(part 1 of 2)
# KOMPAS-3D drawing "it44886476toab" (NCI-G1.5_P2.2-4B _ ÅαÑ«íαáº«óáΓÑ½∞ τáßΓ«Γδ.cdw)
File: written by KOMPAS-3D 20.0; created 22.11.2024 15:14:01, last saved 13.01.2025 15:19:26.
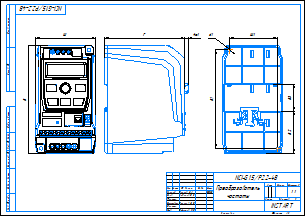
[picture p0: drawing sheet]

Sheet 1: A3, landscape

Document properties: Автор: admin; Полное имя файла: C:\Уралов Работа\Уралов (локальная)\ПЧ\! Китай 3Д-модель NCI\NCI 0.75-2.2 4B\NCI 0.75-2.2 4B.m3d

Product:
- Part/product: it44886476toab
    Масса: 2.32322
  - Body: Тело 17
      Масса: 0.0117014
  - Body: Тело 374
      Масса: 5.48304e-05
  - Body: Тело 265
      Масса: 1.32696e-05
  - Body: Тело 266
      Масса: 1.7366e-05
  - Body: Тело 267
      Масса: 1.7366e-05
  - Body: Тело 103
      Масса: 1.32696e-05
  - Body: Тело 573
      Масса: 4.06595e-05
  - Body: Тело 348
      Масса: 1.32696e-05
  - Body: Тело 270
      Масса: 1.7366e-05
  - Body: Тело 77
      Масса: 1.32696e-05
  - Body: Тело 244
      Масса: 1.65581e-05
  - Body: Тело 536
      Масса: 0.000158536
  - Body: Тело 377
      Масса: 1.65581e-05
  - Body: Тело 272
      Масса: 1.7366e-05
  - Body: Тело 273
      Масса: 5.48304e-05
  - Body: Тело 238
      Масса: 1.7366e-05
  - Body: Тело 274
      Масса: 1.7366e-05
  - Body: Тело 277
      Масса: 1.7366e-05
  - Body: Тело 530
      Масса: 5.61948e-05
  - Body: Тело 278
      Масса: 1.7366e-05
  - Body: Тело 282
      Масса: 1.7366e-05
  - Body: Тело 477
      Масса: 1.51773e-05
  - Body: Тело 526
      Масса: 5.61948e-05
  - Body: Тело 391
      Масса: 1.32696e-05
  - Body: Тело 285
      Масса: 5.48304e-05
  - Body: Тело 287
      Масса: 1.32696e-05
  - Body: Тело 290
      Масса: 0.000413213
  - Body: Тело 269
      Масса: 5.48304e-05
  - Body: Тело 292
      Масса: 1.7366e-05
  - Body: Тело 33
      Масса: 0.00516019
  - Body: Тело 252
      Масса: 5.48304e-05
  - Body: Тело 294
      Масса: 0.000413213
  - Body: Тело 297
      Масса: 3.64631e-05
  - Body: Тело 299
      Масса: 3.64028e-05
  - Body: Тело 283
      Масса: 1.7366e-05
  - Body: Тело 300
      Масса: 1.65581e-05
  - Body: Тело 303
      Масса: 1.65581e-05
  - Body: Тело 516
      Масса: 0.00507377
  - Body: Тело 384
      Масса: 5.48304e-05
  - Body: Тело 360
      Масса: 1.32696e-05
  - Body: Тело 347
      Масса: 1.32696e-05
  - Body: Тело 304
      Масса: 1.65581e-05
  - Body: Тело 307
      Масса: 0.000213463
  - Body: Тело 308
      Масса: 0.000413213
  - Body: Тело 180
      Масса: 1.32696e-05
  - Body: Тело 240
      Масса: 1.7366e-05
  - Body: Тело 309
      Масса: 1.32696e-05
  - Body: Тело 473
      Масса: 0.00425494
  - Body: Тело 311
      Масса: 5.48304e-05
  - Body: Тело 122
      Масса: 1.65581e-05
  - Body: Тело 560
      Масса: 1.65581e-05
  - Body: Тело 312
      Масса: 5.48304e-05
  - Body: Тело 317
      Масса: 1.32696e-05
  - Body: Тело 318
      Масса: 1.32696e-05
  - Body: Тело 321
      Масса: 1.32696e-05
  - Body: Тело 324
      Масса: 1.32696e-05
  - Body: Тело 480
      Масса: 1.51773e-05
  - Body: Тело 288
      Масса: 1.7366e-05
  - Body: Тело 293
      Масса: 5.48304e-05
  - Body: Тело 325
      Масса: 1.32696e-05
  - Body: Тело 99
      Масса: 1.65581e-05
  - Body: Тело 617
      Масса: 1.63919e-05
  - Body: Тело 327
      Масса: 1.32696e-05
  - Body: Тело 31
      Масса: 0.0078835
  - Body: Тело 100
      Масса: 1.65581e-05
  - Body: Тело 105
      Масса: 1.32696e-05
  - Body: Тело 328
      Масса: 1.7366e-05
  - Body: Тело 301
      Масса: 1.65581e-05
  - Body: Тело 331
      Масса: 1.7366e-05
  - Body: Тело 332
      Масса: 1.7366e-05
  - Body: Тело 446
      Масса: 0.000307437
  - Body: Тело 337
      Масса: 1.7366e-05
  - Body: Тело 338
      Масса: 1.7366e-05
  - Body: Тело 570
      Масса: 4.06595e-05
  - Body: Тело 340
      Масса: 1.32696e-05
  - Body: Тело 196
      Масса: 1.32696e-05
  - Body: Тело 357
      Масса: 1.65581e-05
  - Body: Тело 346
      Масса: 1.32696e-05
  - Body: Тело 335
      Масса: 1.32696e-05
  - Body: Тело 281
      Масса: 1.32696e-05
  - Body: Тело 362
      Масса: 1.32696e-05
  - Body: Тело 353
      Масса: 1.7366e-05
  - Body: Тело 355
      Масса: 5.48304e-05
  - Body: Тело 466
      Масса: 0.00829114
  - Body: Тело 358
      Масса: 5.48304e-05
  - Body: Тело 359
      Масса: 1.7366e-05
  - Body: Тело 286
      Масса: 1.7366e-05
  - Body: Тело 86
      Масса: 1.32696e-05
  - Body: Тело 310
      Масса: 1.7366e-05
  - Body: Тело 368
      Масса: 1.32696e-05
  - Body: Тело 370
      Масса: 1.32696e-05
  - Body: Тело 333
      Масса: 1.32696e-05
  - Body: Тело 628
      Масса: 1.51773e-05
  - Body: Тело 371
      Масса: 1.7366e-05
  - Body: Тело 75
      Масса: 1.32696e-05
  - Body: Тело 373
      Масса: 1.32696e-05
  - Body: Тело 375
      Масса: 1.32696e-05
  - Body: Тело 351
      Масса: 2.90876e-05
  - Body: Тело 76
      Масса: 1.65581e-05
  - Body: Тело 259
      Масса: 1.7366e-05
  - Body: Тело 378
      Масса: 0.000413213
  - Body: Тело 95
      Масса: 0.000935996
  - Body: Тело 372
      Масса: 1.7366e-05
  - Body: Тело 322
      Масса: 1.32696e-05
  - Body: Тело 380
      Масса: 1.32696e-05
  - Body: Тело 639
      Масса: 1.63919e-05
  - Body: Тело 385
      Масса: 1.32696e-05
  - Body: Тело 291
      Масса: 0.000213463
  - Body: Тело 386
      Масса: 1.32696e-05
  - Body: Тело 229
      Масса: 1.32696e-05
  - Body: Тело 388
      Масса: 1.32696e-05
  - Body: Тело 389
      Масса: 1.65581e-05
  - Body: Тело 93
      Масса: 3.83377e-05
  - Body: Тело 390
      Масса: 1.65581e-05
  - Body: Тело 143
      Масса: 1.32696e-05
  - Body: Тело 394
      Масса: 1.32696e-05
  - Body: Тело 395
      Масса: 1.32696e-05
  - Body: Тело 354
      Масса: 0.000213463
  - Body: Тело 396
      Масса: 1.7366e-05
  - Body: Тело 397
      Масса: 1.32696e-05
  - Body: Тело 398
      Масса: 1.65581e-05
  - Body: Тело 479
      Масса: 1.51773e-05
  - Body: Тело 402
      Масса: 1.7366e-05
  - Body: Тело 59
      Масса: 1.32696e-05
  - Body: Тело 339
      Масса: 1.32696e-05
  - Body: Тело 404
      Масса: 1.32696e-05
  - Body: Тело 89
      Масса: 0.00142218
  - Body: Тело 406
      Масса: 1.65581e-05
  - Body: Тело 393
      Масса: 1.32696e-05
  - Body: Тело 52
      Масса: 1.32696e-05
  - Body: Тело 407
      Масса: 5.48304e-05
  - Body: Тело 97
      Масса: 0.0015961
  - Body: Тело 410
      Масса: 5.48304e-05
  - Body: Тело 636
      Масса: 1.65581e-05
  - Body: Тело 412
      Масса: 1.7366e-05
  - Body: Тело 413
      Масса: 1.32696e-05
  - Body: Тело 414
      Масса: 1.32696e-05
  - Body: Тело 537
      Масса: 0.000158536
  - Body: Тело 415
      Масса: 1.7366e-05
  - Body: Тело 235
      Масса: 1.7366e-05
  - Body: Тело 419
      Масса: 1.32696e-05
  - Body: Тело 648
      Масса: 0.00426189
  - Body: Тело 420
      Масса: 1.7366e-05
  - Body: Тело 186
      Масса: 1.32696e-05
  - Body: Тело 422
      Масса: 5.48304e-05
  - Body: Тело 381
      Масса: 1.7366e-05
  - Body: Тело 423
      Масса: 1.32696e-05
  - Body: Тело 424
      Масса: 1.7366e-05
  - Body: Тело 98
      Масса: 1.65581e-05
  - Body: Тело 305
      Масса: 1.65581e-05
  - Body: Тело 425
      Масса: 1.32696e-05
  - Body: Тело 365
      Масса: 1.32696e-05
  - Body: Тело 271
      Масса: 1.32696e-05
  - Body: Тело 206
      Масса: 1.32696e-05
  - Body: Тело 429
      Масса: 0.146258
  - Body: Тело 334
      Масса: 1.7366e-05
  - Body: Тело 430
      Масса: 0.146258
  - Body: Тело 350
      Масса: 1.7366e-05
  - Body: Тело 345
      Масса: 1.32696e-05
  - Body: Тело 431
      Масса: 0.146258
  - Body: Тело 364
      Масса: 1.32696e-05
  - Body: Тело 329
      Масса: 1.32696e-05
  - Body: Тело 434
      Масса: 0.000355433
  - Body: Тело 5
      Масса: 0.000355433
  - Body: Тело 124
      Масса: 1.65581e-05
  - Body: Тело 344
      Масса: 1.32696e-05
  - Body: Тело 436
      Масса: 0.000355433
  - Body: Тело 439
      Масса: 0.00113358
  - Body: Тело 606
      Масса: 0.000137594
  - Body: Тело 323
      Масса: 1.32696e-05
  - Body: Тело 441
      Масса: 0.00113358
  - Body: Тело 442
      Масса: 0.000355433
  - Body: Тело 554
      Масса: 4.06595e-05
  - Body: Тело 444
      Масса: 0.000355433
  - Body: Тело 246
      Масса: 1.65581e-05
  - Body: Тело 445
      Масса: 0.00113358
  - Body: Тело 438
      Масса: 0.000355433
  - Body: Тело 106
      Масса: 1.32696e-05
  - Body: Тело 508
      Масса: 1.51773e-05
  - Body: Тело 577
      Масса: 1.7366e-05
  - Body: Тело 392
      Масса: 1.32696e-05
  - Body: Тело 193
      Масса: 1.32696e-05
  - Body: Тело 448
      Масса: 0.000307437
  - Body: Тело 481
      Масса: 1.51773e-05
  - Body: Тело 450
      Масса: 6.34685e-05
  - Body: Тело 222
      Масса: 1.32696e-05
  - Body: Тело 315
      Масса: 1.7366e-05
  - Body: Тело 452
      Масса: 1.63919e-05
  - Body: Тело 53
      Масса: 1.32696e-05
  - Body: Тело 401
      Масса: 1.32696e-05
  - Body: Тело 418
      Масса: 1.7366e-05
  - Body: Тело 517
      Масса: 0.00106884
  - Body: Тело 417
      Масса: 1.32696e-05
  - Body: Тело 453
      Масса: 1.63919e-05
  - Body: Тело 454
      Масса: 0.000382752
  - Body: Тело 428
      Масса: 0.146258
  - Body: Тело 455
      Масса: 1.51773e-05
  - Body: Тело 539
      Масса: 1.51773e-05
  - Body: Тело 457
      Масса: 1.51773e-05
  - Body: Тело 459
      Масса: 3.90329e-05
  - Body: Тело 557
      Масса: 0.00166679
  - Body: Тело 569
      Масса: 1.32696e-05
  - Body: Тело 578
      Масса: 1.32696e-05
  - Body: Тело 626
      Масса: 1.32696e-05
  - Body: Тело 134
      Масса: 1.32696e-05
  - Body: Тело 582
      Масса: 1.65581e-05
  - Body: Тело 203
      Масса: 1.32696e-05
  - Body: Тело 572
      Масса: 1.32696e-05
  - Body: Тело 567
      Масса: 1.32696e-05
  - Body: Тело 207
      Масса: 1.32696e-05
  - Body: Тело 645
      Масса: 1.32696e-05
  - Body: Тело 559
      Масса: 1.65581e-05
  - Body: Тело 152
      Масса: 1.32696e-05
  - Body: Тело 449
      Масса: 0.0658364
  - Body: Тело 316
      Масса: 1.32696e-05
  - Body: Тело 376
      Масса: 1.32696e-05
  - Body: Тело 575
      Масса: 1.32696e-05
  - Body: Тело 576
      Масса: 1.32696e-05
  - Body: Тело 85
      Масса: 1.32696e-05
  - Body: Тело 574
      Масса: 4.06595e-05
  - Body: Тело 399
      Масса: 1.32696e-05
  - Body: Тело 320
      Масса: 1.32696e-05
  - Body: Тело 275
      Масса: 1.7366e-05
  - Body: Тело 213
      Масса: 1.32696e-05
  - Body: Тело 625
      Масса: 1.32696e-05
  - Body: Тело 644
      Масса: 0.000158536
  - Body: Тело 584
      Масса: 4.06595e-05
  - Body: Тело 70
      Масса: 1.65581e-05
  - Body: Тело 588
      Масса: 1.32696e-05
  - Body: Тело 276
      Масса: 1.7366e-05
  - Body: Тело 363
      Масса: 1.32696e-05
  - Body: Тело 474
      Масса: 1.51773e-05
  - Body: Тело 548
      Масса: 2.98222e-05
  - Body: Тело 409
      Масса: 5.48304e-05
  - Body: Тело 472
      Масса: 0.00329327
  - Body: Тело 533
      Масса: 5.61948e-05
  - Body: Тело 647
      Масса: 0.00426189
  - Body: Тело 586
      Масса: 1.32696e-05
  - Body: Тело 262
      Масса: 1.7366e-05
  - Body: Тело 562
      Масса: 0.000382752
  - Body: Тело 379
      Масса: 1.32696e-05
  - Body: Тело 632
      Масса: 1.51773e-05
  - Body: Тело 565
      Масса: 4.06595e-05
  - Body: Тело 118
      Масса: 0.000413213
  - Body: Тело 597
      Масса: 7.12116e-06
  - Body: Тело 613
      Масса: 1.63919e-05
  - Body: Тело 387
      Масса: 1.32696e-05
  - Body: Тело 593
      Масса: 1.32696e-05
  - Body: Тело 408
      Масса: 5.48304e-05
  - Body: Тело 109
      Масса: 1.32696e-05
  - Body: Тело 163
      Масса: 1.32696e-05
  - Body: Тело 488
      Масса: 1.51773e-05
  - Body: Тело 367
      Масса: 1.32696e-05
  - Body: Тело 411
      Масса: 5.48304e-05
  - Body: Тело 583
      Масса: 4.06595e-05
  - Body: Тело 598
      Масса: 7.12116e-06
  - Body: Тело 551
      Масса: 0.000255388
  - Body: Тело 405
      Масса: 1.32696e-05
  - Body: Тело 619
      Масса: 1.32696e-05
  - Body: Тело 361
      Масса: 1.32696e-05
  - Body: Тело 589
      Масса: 1.32696e-05
  - Body: Тело 499
      Масса: 1.51773e-05
  - Body: Тело 440
      Масса: 0.000355433
  - Body: Тело 640
      Масса: 1.63919e-05
  - Body: Тело 150
      Масса: 1.32696e-05
  - Body: Тело 568
      Масса: 1.32696e-05
  - Body: Тело 194
      Масса: 1.32696e-05
  - Body: Тело 251
      Масса: 1.7366e-05
  - Body: Тело 342
      Масса: 0.00166679
  - Body: Тело 604
      Масса: 5.61948e-05
  - Body: Тело 650
      Масса: 0.00426189
  - Body: Тело 161
      Масса: 1.32696e-05
  - Body: Тело 611
      Масса: 0.000158536
  - Body: Тело 210
      Масса: 1.32696e-05
  - Body: Тело 540
      Масса: 1.51773e-05
  - Body: Тело 296
      Масса: 3.6965e-05
  - Body: Тело 601
      Масса: 5.61948e-05
  - Body: Тело 484
      Масса: 0.000158536
  - Body: Тело 622
      Масса: 1.32696e-05
  - Body: Тело 527
      Масса: 0.000141095
  - Body: Тело 624
      Масса: 1.32696e-05
  - Body: Тело 121
      Масса: 0.000413213
  - Body: Тело 600
      Масса: 5.61948e-05
  - Body: Тело 603
      Масса: 5.61948e-05
  - Body: Тело 607
      Масса: 1.32696e-05
  - Body: Тело 289
      Масса: 1.7366e-05
  - Body: Тело 471
      Масса: 0.00329327
  - Body: Тело 313
      Масса: 1.7366e-05
  - Body: Тело 591
      Масса: 7.12116e-06
  - Body: Тело 356
      Масса: 1.65581e-05
  - Body: Тело 306
      Масса: 1.65581e-05
  - Body: Тело 541
      Масса: 0.000158536
  - Body: Тело 511
      Масса: 1.51773e-05
  - Body: Тело 160
      Масса: 1.32696e-05
  - Body: Тело 566
      Масса: 1.32696e-05
  - Body: Тело 563
      Масса: 4.06595e-05
  - Body: Тело 638
      Масса: 1.7366e-05
  - Body: Тело 489
      Масса: 1.51773e-05
  - Body: Тело 456
      Масса: 1.51773e-05
  - Body: Тело 485
      Масса: 0.000158536
  - Body: Тело 284
      Масса: 1.7366e-05
  - Body: Тело 138
      Масса: 2.23009e-05
  - Body: Тело 225
      Масса: 1.32696e-05
  - Body: Тело 546
      Масса: 0.000255388
  - Body: Тело 113
      Масса: 0.000413213
  - Body: Тело 642
      Масса: 3.90329e-05
  - Body: Тело 618
      Масса: 1.63919e-05
  - Body: Тело 525
      Масса: 0.000213463
  - Body: Тело 164
      Масса: 1.32696e-05
  - Body: Тело 253
      Масса: 1.7366e-05
  - Body: Тело 561
      Масса: 1.65581e-05
  - Body: Тело 594
      Масса: 1.32696e-05
  - Body: Тело 482
      Масса: 1.51773e-05
  - Body: Тело 81
      Масса: 1.32696e-05
  - Body: Тело 280
      Масса: 1.32696e-05
  - Body: Тело 494
      Масса: 1.51773e-05
  - Body: Тело 641
      Масса: 3.90329e-05
  - Body: Тело 564
      Масса: 4.06595e-05
  - Body: Тело 633
      Масса: 1.51773e-05
  - Body: Тело 518
      Масса: 0.00166679
  - Body: Тело 620
      Масса: 1.7366e-05
  - Body: Тело 497
      Масса: 1.51773e-05
  - Body: Тело 151
      Масса: 1.65581e-05
  - Body: Тело 302
      Масса: 1.65581e-05
  - Body: Тело 110
      Масса: 1.32696e-05
  - Body: Тело 646
      Масса: 0.000137594
  - Body: Тело 264
      Масса: 1.7366e-05
  - Body: Тело 635
      Масса: 1.65581e-05
  - Body: Тело 608
      Масса: 0.00166679
  - Body: Тело 460
      Масса: 3.90329e-05
  - Body: Тело 403
      Масса: 1.7366e-05
  - Body: Тело 612
      Масса: 0.000158536
  - Body: Тело 492
      Масса: 1.51773e-05
  - Body: Тело 139
      Масса: 0.000194606
  - Body: Тело 400
      Масса: 1.7366e-05
  - Body: Тело 605
      Масса: 5.61948e-05
  - Body: Тело 623
      Масса: 1.32696e-05
  - Body: Тело 117
      Масса: 0.000413213
  - Body: Тело 185
      Масса: 1.32696e-05
  - Body: Тело 631
      Масса: 1.51773e-05
  - Body: Тело 580
      Масса: 1.32696e-05
  - Body: Тело 349
      Масса: 1.7366e-05
  - Body: Тело 621
      Масса: 1.32696e-05
  - Body: Тело 627
      Масса: 0.000255388
  - Body: Тело 531
      Масса: 5.61948e-05
  - Body: Тело 649
      Масса: 0.00426189
  - Body: Тело 585
      Масса: 4.06595e-05
  - Body: Тело 236
      Масса: 1.7366e-05
  - Body: Тело 513
      Масса: 1.51773e-05
  - Body: Тело 426
      Масса: 1.32696e-05
  - Body: Тело 341
      Масса: 0.00166679
  - Body: Тело 470
      Масса: 0.00329329
  - Body: Тело 382
      Масса: 5.48304e-05
  - Body: Тело 227
      Масса: 1.32696e-05
  - Body: Тело 476
      Масса: 1.51773e-05
  - Body: Тело 538
      Масса: 1.51773e-05
  - Body: Тело 596
      Масса: 1.32696e-05
  - Body: Тело 609
      Масса: 1.7366e-05
  - Body: Тело 610
      Масса: 0.00166679
  - Body: Тело 263
      Масса: 1.7366e-05
  - Body: Тело 629
      Масса: 1.51773e-05
  - Body: Тело 336
      Масса: 3.64028e-05
  - Body: Тело 495
      Масса: 1.51773e-05
  - Body: Тело 168
      Масса: 1.32696e-05
  - Body: Тело 298
      Масса: 3.64495e-05
  - Body: Тело 279
      Масса: 1.32696e-05
  - Body: Тело 72
      Масса: 1.65581e-05
  - Body: Тело 500
      Масса: 1.51773e-05
  - Body: Тело 505
      Масса: 1.51773e-05
  - Body: Тело 558
      Масса: 0.00726683
  - Body: Тело 630
      Масса: 1.51773e-05
  - Body: Тело 602
      Масса: 5.61948e-05
  - Body: Тело 556
      Масса: 0.00166679
  - Body: Тело 555
      Масса: 0.00166679
  - Body: Тело 634
      Масса: 1.51773e-05
  - Body: Тело 435
      Масса: 0.00113358
  - Body: Тело 416
      Масса: 1.7366e-05
  - Body: Тело 190
      Масса: 1.32696e-05
  - Body: Тело 330
      Масса: 1.7366e-05
  - Body: Тело 28
      Масса: 0.00135688
  - Body: Тело 553
      Масса: 4.06595e-05
  - Body: Тело 176
      Масса: 1.32696e-05
  - Body: Тело 552
      Масса: 4.06595e-05
  - Body: Тело 534
      Масса: 1.32696e-05
  - Body: Тело 595
      Масса: 1.32696e-05
  - Body: Тело 23
      Масса: 0.0243258
  - Body: Тело 247
      Масса: 1.7366e-05
  - Body: Тело 314
      Масса: 1.7366e-05
  - Body: Тело 126
      Масса: 0.000512664
  - Body: Тело 157
      Масса: 1.32696e-05
  - Body: Тело 550
      Масса: 0.000255388
  - Body: Тело 32
      Масса: 0.0135217
  - Body: Тело 592
      Масса: 7.12116e-06
  - Body: Тело 366
      Масса: 1.7366e-05
  - Body: Тело 504
      Масса: 1.51773e-05
  - Body: Тело 258
      Масса: 1.7366e-05
  - Body: Тело 421
      Масса: 1.7366e-05
  - Body: Тело 35
      Масса: 0.262997
  - Body: Тело 204
      Масса: 1.32696e-05
  - Body: Тело 549
      Масса: 0.000255388
  - Body: Тело 257
      Масса: 1.7366e-05
  - Body: Тело 614
      Масса: 1.63919e-05
  - Body: Тело 547
      Масса: 0.000255388
  - Body: Тело 41
      Масса: 0.0119524
  - Body: Тело 71
      Масса: 1.65581e-05
  - Body: Тело 506
      Масса: 1.51773e-05
  - Body: Тело 545
      Масса: 1.51773e-05
  - Body: Тело 145
      Масса: 1.32696e-05
  - Body: Тело 461
      Масса: 0.000404362
  - Body: Тело 502
      Масса: 1.51773e-05
  - Body: Тело 352
      Масса: 2.90876e-05
  - Body: Тело 120
      Масса: 0.000413213
  - Body: Тело 295
      Масса: 1.65581e-05
  - Body: Тело 544
      Масса: 0.000158536
  - Body: Тело 469
      Масса: 0.0113891
  - Body: Тело 146
      Масса: 1.32696e-05
  - Body: Тело 149
      Масса: 1.32696e-05
  - Body: Тело 615
      Масса: 1.63919e-05
  - Body: Тело 543
      Масса: 0.000158536
  - Body: Тело 542
      Масса: 0.000158536
  - Body: Тело 462
      Масса: 0.000404362
  - Body: Тело 616
      Масса: 1.63919e-05
  - Body: Тело 343
      Масса: 0.00166679
  - Body: Тело 532
      Масса: 5.61948e-05
  - Body: Тело 493
      Масса: 1.51773e-05
  - Body: Тело 529
      Масса: 5.61948e-05
  - Body: Тело 579
      Масса: 0.00017125
  - Body: Тело 200
      Масса: 1.32696e-05
  - Body: Тело 239
      Масса: 5.48304e-05
  - Body: Тело 443
      Масса: 0.00113358
  - Body: Тело 216
      Масса: 0.000280294
  - Body: Тело 468
      Масса: 0.0253857
  - Body: Тело 64
      Масса: 1.65581e-05
  - Body: Тело 528
      Масса: 0.000141095
  - Body: Тело 599
      Масса: 7.12116e-06
  - Body: Тело 590
      Масса: 1.32696e-05
  - Body: Тело 191
      Масса: 1.32696e-05
  - Body: Тело 523
      Масса: 0.000255388
  - Body: Тело 458
      Масса: 1.51773e-05
  - Body: Тело 319
      Масса: 1.32696e-05
  - Body: Тело 49
      Масса: 0.00944
  - Body: Тело 522
      Масса: 1.65581e-05
  - Body: Тело 521
      Масса: 1.32696e-05
  - Body: Тело 571
      Масса: 0.00166679
  - Body: Тело 509
      Масса: 1.51773e-05
  - Body: Тело 326
      Масса: 1.32696e-05
  - Body: Тело 520
      Масса: 5.48304e-05
  - Body: Тело 427
      Масса: 1.32696e-05
  - Body: Тело 519
      Масса: 1.7366e-05
  - Body: Тело 637
      Масса: 1.51773e-05
  - Body: Тело 524
      Масса: 1.65581e-05
  - Body: Тело 432
      Масса: 0.000118347
  - Body: Тело 487
      Масса: 1.65581e-05
  - Body: Тело 510
      Масса: 1.51773e-05
  - Body: Тело 515
      Масса: 0.00507372
  - Body: Тело 512
      Масса: 1.51773e-05
  - Body: Тело 155
      Масса: 1.32696e-05
  - Body: Тело 587
      Масса: 1.32696e-05
  - Body: Тело 174
      Масса: 1.65581e-05
  - Body: Тело 507
      Масса: 1.51773e-05
  - Body: Тело 12
      Масса: 0.000703761
  - Body: Тело 187
      Масса: 1.32696e-05
  - Body: Тело 447
      Масса: 0.000307437
  - Body: Тело 503
      Масса: 1.51773e-05
  - Body: Тело 501
      Масса: 1.51773e-05
  - Body: Тело 369
      Масса: 1.32696e-05
  - Body: Тело 60
      Масса: 1.32696e-05
  - Body: Тело 498
      Масса: 1.51773e-05
  - Body: Тело 535
      Масса: 1.52051e-05
  - Body: Тело 437
      Масса: 0.00113358
  - Body: Тело 496
      Масса: 1.51773e-05
  - Body: Тело 433
      Масса: 0.000118347
  - Body: Тело 491
      Масса: 1.65581e-05
  - Body: Тело 490
      Масса: 1.51773e-05
  - Body: Тело 581
      Масса: 1.65581e-05
  - Body: Тело 486
      Масса: 0.000158536
  - Body: Тело 483
      Масса: 1.51773e-05
  - Body: Тело 514
      Масса: 1.51773e-05
  - Body: Тело 643
      Масса: 0.000158536
  - Body: Тело 125
      Масса: 1.65581e-05
  - Body: Тело 383
      Масса: 0.000340816
  - Body: Тело 465
      Масса: 0.00829114
  - Body: Тело 478
      Масса: 1.51773e-05
  - Body: Тело 451
      Масса: 6.34685e-05
  - Body: Тело 475
      Масса: 1.51773e-05
  - Body: Тело 467
      Масса: 0.00436982
  - Body: Тело 268
      Масса: 5.48304e-05
  - Body: Тело 464
      Масса: 0.00829425
  - Body: Тело 226
      Масса: 0.000413213
  - Body: Тело 463
      Масса: 0.000404362
  - Body: Тело 170
      Масса: 1.32696e-05
  - Body: Тело 261
      Масса: 3.83377e-05
  - Body: Тело 260
      Масса: 1.7366e-05
  - Body: Тело 167
      Масса: 1.32696e-05
  - Body: Тело 256
      Масса: 1.7366e-05
  - Body: Тело 119
      Масса: 0.000413213
  - Body: Тело 255
      Масса: 1.7366e-05
  - Body: Тело 254
      Масса: 1.32696e-05
  - Body: Тело 250
      Масса: 1.7366e-05
  - Body: Тело 249
      Масса: 1.7366e-05
  - Body: Тело 248
      Масса: 1.7366e-05
  - Body: Тело 19
      Масса: 0.0117014
  - Body: Тело 114
      Масса: 0.000413213
  - Body: Тело 234
      Масса: 1.7366e-05
  - Body: Тело 245
      Масса: 1.65581e-05
  - Body: Тело 243
      Масса: 1.65581e-05
  - Body: Тело 242
      Масса: 1.65581e-05
  - Body: Тело 65
      Масса: 1.65581e-05
  - Body: Тело 241
      Масса: 0.000424983
  - Body: Тело 141
      Масса: 0.000213463
  - Body: Тело 237
      Масса: 1.7366e-05
  - Body: Тело 1
      Масса: 0.00113358
  - Body: Тело 233
      Масса: 1.7366e-05
  - Body: Тело 232
      Масса: 5.48304e-05
  - Body: Тело 231
      Масса: 0.00398049
  - Body: Тело 230
      Масса: 1.32696e-05
  - Body: Тело 184
      Масса: 1.32696e-05
  - Body: Тело 228
      Масса: 1.32696e-05
  - Body: Тело 224
      Масса: 1.32696e-05
  - Body: Тело 162
      Масса: 1.65581e-05
  - Body: Тело 223
      Масса: 1.32696e-05
  - Body: Тело 221
      Масса: 1.65581e-05
  - Body: Тело 220
      Масса: 1.32696e-05
  - Body: Тело 219
      Масса: 1.32696e-05
  - Body: Тело 218
      Масса: 1.32696e-05
  - Body: Тело 217
      Масса: 1.32696e-05
  - Body: Тело 215
      Масса: 1.65581e-05
  - Body: Тело 9
      Масса: 0.000703761
  - Body: Тело 214
      Масса: 1.32696e-05
  - Body: Тело 212
      Масса: 1.32696e-05
  - Body: Тело 211
      Масса: 1.32696e-05
  - Body: Тело 209
      Масса: 1.32696e-05
  - Body: Тело 208
      Масса: 1.7366e-05
  - Body: Тело 205
      Масса: 1.32696e-05
  - Body: Тело 202
      Масса: 1.32696e-05
  - Body: Тело 201
      Масса: 1.32696e-05
  - Body: Тело 29
      Масса: 0.00135688
  - Body: Тело 199
      Масса: 1.32696e-05
  - Body: Тело 198
      Масса: 1.32696e-05
  - Body: Тело 197
      Масса: 1.32696e-05
  - Body: Тело 195
      Масса: 1.32696e-05
  - Body: Тело 192
      Масса: 1.32696e-05
  - Body: Тело 189
      Масса: 1.32696e-05
  - Body: Тело 188
      Масса: 1.32696e-05
  - Body: Тело 183
      Масса: 1.32696e-05
  - Body: Тело 182
      Масса: 1.32696e-05
  - Body: Тело 181
      Масса: 1.32696e-05
  - Body: Тело 179
      Масса: 1.32696e-05
  - Body: Тело 178
      Масса: 1.32696e-05
  - Body: Тело 44
      Масса: 0.0119524
  - Body: Тело 50
      Масса: 0.00101975
  - Body: Тело 177
      Масса: 1.32696e-05
  - Body: Тело 175
      Масса: 1.32696e-05
  - Body: Тело 45
      Масса: 0.0267013
  - Body: Тело 137
      Масса: 1.32696e-05
  - Body: Тело 173
      Масса: 1.32696e-05
  - Body: Тело 172
      Масса: 1.65581e-05
  - Body: Тело 153
      Масса: 1.32696e-05
  - Body: Тело 171
      Масса: 1.32696e-05
  - Body: Тело 169
      Масса: 1.32696e-05
  - Body: Тело 140
      Масса: 0.000213463
  - Body: Тело 166
      Масса: 1.32696e-05
  - Body: Тело 165
      Масса: 1.65581e-05
  - Body: Тело 159
      Масса: 1.32696e-05
  - Body: Тело 116
      Масса: 0.000413213
  - Body: Тело 158
      Масса: 1.32696e-05
  - Body: Тело 156
      Масса: 1.32696e-05
  - Body: Тело 154
      Масса: 1.32696e-05
  - Body: Тело 148
      Масса: 1.32696e-05
  - Body: Тело 147
      Масса: 1.32696e-05
  - Body: Тело 24
      Масса: 0.0110484
  - Body: Тело 62
      Масса: 1.32696e-05
  - Body: Тело 144
      Масса: 1.32696e-05
  - Body: Тело 142
      Масса: 0.000213463
  - Body: Тело 136
      Масса: 1.32696e-05
  - Body: Тело 135
      Масса: 1.32696e-05
  - Body: Тело 38
      Масса: 0.00631989
  - Body: Тело 133
      Масса: 1.32696e-05
  - Body: Тело 132
      Масса: 1.32696e-05
  - Body: Тело 131
      Масса: 1.32696e-05
  - Body: Тело 16
      Масса: 0.000703761
  - Body: Тело 130
      Масса: 1.32696e-05
  - Body: Тело 112
      Масса: 0.000413213
  - Body: Тело 129
      Масса: 1.32696e-05
  - Body: Тело 128
      Масса: 1.32696e-05
  - Body: Тело 127
      Масса: 1.32696e-05
  - Body: Тело 123
      Масса: 1.65581e-05
  - Body: Тело 115
      Масса: 0.000413213
  - Body: Тело 111
      Масса: 0.000194606
  - Body: Тело 108
      Масса: 1.32696e-05
  - Body: Тело 107
      Масса: 1.32696e-05
  - Body: Тело 104
      Масса: 1.32696e-05
  - Body: Тело 102
      Масса: 1.32696e-05
  - Body: Тело 90
      Масса: 0.000966482
  - Body: Тело 101
      Масса: 1.32696e-05
  - Body: Тело 96
      Масса: 0.00181049
  - Body: Тело 94
      Масса: 0.00554276
  - Body: Тело 92
      Масса: 3.83377e-05
  - Body: Тело 91
      Масса: 0.0246688
  - Body: Тело 15
      Масса: 0.000703761
  - Body: Тело 88
      Масса: 0.000873873
  - Body: Тело 87
      Масса: 0.000966482
  - Body: Тело 84
      Масса: 1.32696e-05
  - Body: Тело 83
      Масса: 1.32696e-05
  - Body: Тело 82
      Масса: 1.32696e-05
  - Body: Тело 80
      Масса: 1.32696e-05
  - Body: Тело 79
      Масса: 1.32696e-05
  - Body: Тело 78
      Масса: 1.65581e-05
  - Body: Тело 74
      Масса: 1.65581e-05
  - Body: Тело 48
      Масса: 0.00853877
  - Body: Тело 73
      Масса: 1.65581e-05
  - Body: Тело 69
      Масса: 1.65581e-05
  - Body: Тело 68
      Масса: 1.65581e-05
  - Body: Тело 67
      Масса: 1.65581e-05
  - Body: Тело 66
      Масса: 1.65581e-05
  - Body: Тело 63
      Масса: 1.65581e-05
  - Body: Тело 57
      Масса: 1.32696e-05
  - Body: Тело 61
      Масса: 1.32696e-05
  - Body: Тело 58
      Масса: 1.32696e-05
  - Body: Тело 56
      Масса: 1.32696e-05
  - Body: Тело 55
      Масса: 1.32696e-05
  - Body: Тело 54
      Масса: 1.32696e-05
  - Body: Тело 51
      Масса: 1.32696e-05
  - Body: Тело 47
      Масса: 0.551587
  - Body: Тело 46
      Масса: 0.0119034
  - Body: Тело 43
      Масса: 0.0119524
  - Body: Тело 42
      Масса: 0.0119524
  - Body: Тело 40
      Масса: 0.0119524
  - Body: Тело 39
      Масса: 0.0119524
  - Body: Тело 37
      Масса: 0.0343584
  - Body: Тело 36
      Масса: 0.0668131
  - Body: Тело 34
      Масса: 0.00831628
  - Body: Тело 30
      Масса: 0.000935996
  - Body: Тело 27
      Масса: 0.00135688
  - Body: Тело 26
      Масса: 0.00135688
  - Body: Тело 25
      Масса: 0.00135688
  - Body: Тело 22
      Масса: 0.0636504
  - Body: Тело 21
      Масса: 0.0864411
  - Body: Тело 20
      Масса: 0.120334
  - Body: Тело 18
      Масса: 0.0117014
  - Body: Тело 14
      Масса: 0.000703761
  - Body: Тело 13
      Масса: 0.000703761
  - Body: Тело 11
      Масса: 0.000703761
  - Body: Тело 10
      Масса: 0.0160396
  - Body: Тело 8
      Масса: 0.000703761
  - Body: Тело 7
      Масса: 0.000703761
  - Body: Тело 6
      Масса: 0.000355433
  - Body: Тело 4
      Масса: 0.000355433
  - Body: Тело 3
      Масса: 0.00113358
  - Body: Тело 2
      Масса: 0.00113358

Title block, sheet 1: Наименование: Преобразователь / частоты; designation: NCI-G1.5/P2.2-4B; Количество листов документа: 1; organisation: INSTART; cell 10: Согласовано; Форматы листов документа: A3; stored path: P:\INSTART\Технический отдел\ОР\Прочие задачи\КД на номенклатурный ряд\КД на типоразмеры ПЧ\NCI\NCI-G0.75_P1.5-4B\NCI-G0.75_P1.5-4B _ Преобразователь частоты.cdw; Разработал: Уралов Д.А.; Проверил: Андреев Н.В.; Подписал: Смелков Ж.Е.; Утвердил: Ефремов И.Н.; Разработал, date: 13.01.25

Views: Вид 1
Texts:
  Кривая без истории:10000
  Кривая без истории:10001
  Кривая без истории:10002
  Кривая без истории:10003
  Кривая без истории:10004
  Кривая без истории:10005
  Кривая без истории:10006
  Кривая без истории:10007
  Кривая без истории:10008
  Кривая без истории:10009
  Кривая без истории:10010
  Кривая без истории:10011
  Кривая без истории:10012
  Кривая без истории:10013
  Кривая без истории:10014
  Кривая без истории:10015
  Кривая без истории:10016
  Кривая без истории:10017
  Кривая без истории:10018
  Кривая без истории:10019
  Кривая без истории:10020
  Кривая без истории:10021
  Кривая без истории:10022
  Кривая без истории:10023
  Кривая без истории:10024
  Кривая без истории:10025
  Кривая без истории:10026
  Кривая без истории:10027
  Кривая без истории:10028
  Кривая без истории:10029
  Кривая без истории:10030
  Кривая без истории:10031
  Кривая без истории:10032
  Кривая без истории:10033
  Кривая без истории:10034
  Кривая без истории:10035
  Кривая без истории:10036
  Кривая без истории:10037
  Кривая без истории:10038
  Кривая без истории:10039
  Кривая без истории:10040
  Кривая без истории:10041
  Кривая без истории:10042
  Кривая без истории:10043
  Кривая без истории:10044
  Кривая без истории:10045
  Кривая без истории:10046
  Кривая без истории:10047
  Кривая без истории:10048
  Кривая без истории:10049
  Кривая без истории:10050
  Кривая без истории:10051
  Кривая без истории:10052
  Кривая без истории:10053
  Кривая без истории:10054
  Кривая без истории:10055
  Кривая без истории:10056
  Кривая без истории:10057
  Кривая без истории:10058
  Кривая без истории:10059
  Кривая без истории:10060
  Кривая без истории:10061
  Кривая без истории:10062
  Кривая без истории:10063
  Кривая без истории:10064
  Кривая без истории:10065
  Кривая без истории:10066
  Кривая без истории:10067
  Кривая без истории:10068
  Кривая без истории:10069
  Кривая без истории:10070
  Кривая без истории:10071
  Кривая без истории:10072
  Кривая без истории:10073
  Кривая без истории:10074
  Кривая без истории:10075
  Кривая без истории:10076
  Кривая без истории:10077
  Кривая без истории:10078
  Кривая без истории:10079
  Кривая без истории:10080
  Кривая без истории:10081
  Кривая без истории:10082
  Кривая без истории:10083
  Кривая без истории:10084
  Кривая без истории:10085
  Кривая без истории:10086
  Кривая без истории:10087
  Кривая без истории:10088
  Кривая без истории:10089
  Кривая без истории:10090
  Кривая без истории:10091
  Кривая без истории:10092
  Кривая без истории:10093
  Кривая без истории:10094
  Кривая без истории:10095
  Кривая без истории:10096
  Кривая без истории:10097
  Кривая без истории:10098
  Кривая без истории:10099
  Кривая без истории:10100
  Кривая без истории:10101
  Кривая без истории:10102
  Кривая без истории:10103
  Кривая без истории:10104
  Кривая без истории:10105
  Кривая без истории:10106
  Кривая без истории:10107
  Кривая без истории:10108
  Кривая без истории:10109
  Кривая без истории:10110
  Кривая без истории:10111
  Кривая без истории:10112
  Кривая без истории:10113
  Кривая без истории:10114
  Кривая без истории:10115
  Кривая без истории:10116
  Кривая без истории:10117
  Кривая без истории:10118
  Кривая без истории:10119
  Кривая без истории:10120
  Кривая без истории:10121
  Кривая без истории:10122
  Кривая без истории:10123
  Кривая без истории:10124
  Кривая без истории:10125
  Кривая без истории:10126
  Кривая без истории:10127
  Кривая без истории:10128
  Кривая без истории:10129
  Кривая без истории:10130
  Кривая без истории:10131
  Кривая без истории:10132
  Кривая без истории:10133
  Кривая без истории:10134
  Кривая без истории:10135
  Кривая без истории:10136
  Кривая без истории:10137
  Кривая без истории:10138
  Кривая без истории:10139
  Кривая без истории:10140
  Кривая без истории:10141
  Кривая без истории:10142
  Кривая без истории:10143
  Кривая без истории:10144
  Кривая без истории:10145
  Кривая без истории:10146
  Кривая без истории:10147
  Кривая без истории:10148
  Кривая без истории:10149
  Кривая без истории:10150
  Кривая без истории:10151
  Кривая без истории:10152
  Кривая без истории:10153
  Кривая без истории:10154
  Кривая без истории:10155
  Кривая без истории:10156
  Кривая без истории:10157
  Кривая без истории:10158
  Кривая без истории:10159
  Кривая без истории:10160
  Кривая без истории:10161
  Кривая без истории:10162
  Кривая без истории:10163
  Кривая без истории:10164
  Кривая без истории:10165
  Кривая без истории:10166
  Кривая без истории:10167
  Кривая без истории:10168
  Кривая без истории:10169
  Кривая без истории:10170
  Кривая без истории:10171
  Кривая без истории:10172
  Кривая без истории:10173
  Кривая без истории:10174
  Кривая без истории:10175
  Кривая без истории:10176
  Кривая без истории:10177
  Кривая без истории:10178
  Кривая без истории:10179
  Кривая без истории:10180
  Кривая без истории:10181
  Кривая без истории:10182
  Кривая без истории:10183
  Кривая без истории:10184
  Кривая без истории:10185
  Кривая без истории:10186
  Кривая без истории:10187
  Кривая без истории:10188
  Кривая без истории:10189
  Кривая без истории:10190
  Кривая без истории:10191
  Кривая без истории:10192
  Кривая без истории:10193
  Кривая без истории:10194
  Кривая без истории:10195
  Кривая без истории:10196
  Кривая без истории:10197
  Кривая без истории:10198
  Кривая без истории:10199
  Кривая без истории:10200
  Кривая без истории:10201
  Кривая без истории:10202
  Кривая без истории:10203
  Кривая без истории:10204
  Кривая без истории:10205
  Кривая без истории:10206
  Кривая без истории:10207
  Кривая без истории:10208
  Кривая без истории:10209
  Кривая без истории:10210
  Кривая без истории:10211
  Кривая без истории:10212
  Кривая без истории:10213
  Кривая без истории:10214
  Кривая без истории:10215
  Кривая без истории:10216
  Кривая без истории:10217
  Кривая без истории:10218
  Кривая без истории:10219
  Кривая без истории:10220
  Кривая без истории:10221
  Кривая без истории:10222
  Кривая без истории:10223
  Кривая без истории:10224
  Кривая без истории:10225
  Кривая без истории:10226
  Кривая без истории:10227
  Кривая без истории:10228
  Кривая без истории:10229
  Кривая без истории:10230
  Кривая без истории:10231
  Кривая без истории:10232
  Кривая без истории:10233
  Кривая без истории:10234
  Кривая без истории:10235
  Кривая без истории:10236
  Кривая без истории:10237
  Кривая без истории:10238
  Кривая без истории:10239
  Кривая без истории:10240
  Кривая без истории:10241
  Кривая без истории:10242
  Кривая без истории:10243
  Кривая без истории:10244
  Кривая без истории:10245
  Кривая без истории:10246
  Кривая без истории:10247
  Кривая без истории:10248
  Кривая без истории:10249
  Кривая без истории:10250
  Кривая без истории:10251
  Кривая без истории:10252
  Кривая без истории:10253
  Кривая без истории:10254
  Кривая без истории:10255
  Кривая без истории:10256
  Кривая без истории:10257
  Кривая без истории:10258
  Кривая без истории:10259
  Кривая без истории:10260
  Кривая без истории:10261
  Кривая без истории:10262
  Кривая без истории:10263
  Кривая без истории:10264
  Кривая без истории:10265
  Кривая без истории:10266
  Кривая без истории:10267
  Кривая без истории:10268
  Кривая без истории:10269
  Кривая без истории:10270
  Кривая без истории:10271
  Кривая без истории:10272
  Кривая без истории:10273
  Кривая без истории:10274
  Кривая без истории:10275
  Кривая без истории:10276
  Кривая без истории:10277
  Кривая без истории:10278
  Кривая без истории:10279
  Кривая без истории:10280
  Кривая без истории:10281
  Кривая без истории:10282
  Кривая без истории:10283
  Кривая без истории:10284
  Кривая без истории:10285
  Кривая без истории:10286
  Кривая без истории:10287
  Кривая без истории:10288
  Кривая без истории:10289
  Кривая без истории:10290
  Кривая без истории:10291
  Кривая без истории:10292
  Кривая без истории:10293
  Кривая без истории:10294
  Кривая без истории:10295
  Кривая без истории:10296
  Кривая без истории:10297
  Кривая без истории:10298
  Кривая без истории:10299
  Кривая без истории:10300
  Кривая без истории:10301
  Кривая без истории:10302
  Кривая без истории:10303
  Кривая без истории:10304
  Кривая без истории:10305
  Кривая без истории:10306
  Кривая без истории:10307
  Кривая без истории:10308
  Кривая без истории:10309
  Кривая без истории:10310
  Кривая без истории:10311
  Кривая без истории:10312
  Кривая без истории:10313
  Кривая без истории:10314
  Кривая без истории:10315
  Кривая без истории:10316
  Кривая без истории:10317
  Кривая без истории:10318
  Кривая без истории:10319
  Кривая без истории:10320
  Кривая без истории:10321
  Кривая без истории:10322
  Кривая без истории:10323
  Кривая без истории:10324
  Кривая без истории:10325
  Кривая без истории:10326
  Кривая без истории:10327
  Кривая без истории:10328
  Кривая без истории:10329
  Кривая без истории:10330
  Кривая без истории:10331
  Кривая без истории:10332
  Кривая без истории:10333
  Кривая без истории:10334
  Кривая без истории:10335
  Кривая без истории:10336
  Кривая без истории:10337
  Кривая без истории:10338
  Кривая без истории:10339
  Кривая без истории:10340
  Кривая без истории:10341
  Кривая без истории:10342
  Кривая без истории:10343
  Кривая без истории:10344
  Кривая без истории:10345
  Кривая без истории:10346
  Кривая без истории:10347
  Кривая без истории:10348
  Кривая без истории:10349
  Кривая без истории:10350
  Кривая без истории:10351
  Кривая без истории:10352
  Кривая без истории:10353
  Кривая без истории:10354
  Кривая без истории:10355
  Кривая без истории:10356
  Кривая без истории:10357
  Кривая без истории:10358
  Кривая без истории:10359
  Кривая без истории:10360
  Кривая без истории:10361
  Кривая без истории:10362
  Кривая без истории:10363
  Кривая без истории:10364
  Кривая без истории:10365
  Кривая без истории:10366
  Кривая без истории:10367
  Кривая без истории:10368
  Кривая без истории:10369
  Кривая без истории:10370
  Кривая без истории:10371
  Кривая без истории:10372
  Кривая без истории:10373
  Кривая без истории:10374
  Кривая без истории:10375
  Кривая без истории:10376
  Кривая без истории:10377
  Кривая без истории:10378
  Кривая без истории:10379
  Кривая без истории:10380
  Кривая без истории:10381
  Кривая без истории:10382
  Кривая без истории:10383
  Кривая без истории:10384
  Кривая без истории:10385
  Кривая без истории:10386
  Кривая без истории:10387
  Кривая без истории:10388
  Кривая без истории:10389
  Кривая без истории:10390
  Кривая без истории:10391
  Кривая без истории:10392
  Кривая без истории:10393
  Кривая без истории:10394
  Кривая без истории:10395
  Кривая без истории:10396
  Кривая без истории:10397
  Кривая без истории:10398
  Кривая без истории:10399
  Кривая без истории:10400
  Кривая без истории:10401
  Кривая без истории:10402
  Кривая без истории:10403
  Кривая без истории:10404
  Кривая без истории:10405
  Кривая без истории:10406
  Кривая без истории:10407
  Кривая без истории:10408
  Кривая без истории:10409
  Кривая без истории:10410
  Кривая без истории:10411
  Кривая без истории:10412
  Кривая без истории:10413
  Кривая без истории:10414
  Кривая без истории:10415
  Кривая без истории:10416
  Кривая без истории:10417
  Кривая без истории:10418
  Кривая без истории:10419
  Кривая без истории:10420
  Кривая без истории:10421
  Кривая без истории:10422
  Кривая без истории:10423
  Кривая без истории:10424
  Кривая без истории:10425
  Кривая без истории:10426
  Кривая без истории:10427
  Кривая без истории:10428
  Кривая без истории:10429
  Кривая без истории:10430
  Кривая без истории:10431
  Кривая без истории:10432
  Кривая без истории:10433
  Кривая без истории:10434
  Кривая без истории:10435
  Кривая без истории:10436
  Кривая без истории:10437
  Кривая без истории:10438
  Кривая без истории:10439
  Кривая без истории:10440
  Кривая без истории:10441
  Кривая без истории:10442
  Кривая без истории:10443
  Кривая без истории:10444
  Кривая без истории:10445
  Кривая без истории:10446
  Кривая без истории:10447
  Кривая без истории:10448
  Кривая без истории:10449
  Кривая без истории:10450
  Кривая без истории:10451
  Кривая без истории:10452
  Кривая без истории:10453
  Кривая без истории:10454
  Кривая без истории:10455
  Кривая без истории:10456
  Кривая без истории:10457
  Кривая без истории:10458
  Кривая без истории:10459
  Кривая без истории:10460
  Кривая без истории:10461
  Кривая без истории:10462
  Кривая без истории:10463
  Кривая без истории:10464
  Кривая без истории:10465
  Кривая без истории:10466
  Кривая без истории:10467
  Кривая без истории:10468
  Кривая без истории:10469
  Кривая без истории:10470
  Кривая без истории:10471
  Кривая без истории:10472
  Кривая без истории:10473
  Кривая без истории:10474
  Кривая без истории:10475
  Кривая без истории:10476
  Кривая без истории:10477
  Кривая без истории:10478
  Кривая без истории:10479
  Кривая без истории:10480
  Кривая без истории:10481
  Кривая без истории:10482
  Кривая без истории:10483
  Кривая без истории:10484
  Кривая без истории:10485
  Кривая без истории:10486
  Кривая без истории:10487
  Кривая без истории:10488
  Кривая без истории:10489
  Кривая без истории:10490
  Кривая без истории:10491
  Кривая без истории:10492
  Кривая без истории:10493
  Кривая без истории:10494
  Кривая без истории:10495
  Кривая без истории:10496
  Кривая без истории:10497
  Кривая без истории:10498
  Кривая без истории:10499
  Кривая без истории:10500
  Кривая без истории:10501
  Кривая без истории:10502
  Кривая без истории:10503
  Кривая без истории:10504
  Кривая без истории:10505
  Кривая без истории:10506
  Кривая без истории:10507
  Кривая без истории:10508
  Кривая без истории:10509
  Кривая без истории:10510
  Кривая без истории:10511
  Кривая без истории:10512
  Кривая без истории:10513
  Кривая без истории:10514
  Кривая без истории:10515
  Кривая без истории:10516
  Кривая без истории:10517
  Кривая без истории:10518
  Кривая без истории:10519
  Кривая без истории:10520
  Кривая без истории:10521
  Кривая без истории:10522
  Кривая без истории:10523
  Кривая без истории:10524
  Кривая без истории:10525
  Кривая без истории:10526
  Кривая без истории:10527
  Кривая без истории:10528
  Кривая без истории:10529
  Кривая без истории:10530
  Кривая без истории:10531
  Кривая без истории:10532
  Кривая без истории:10533
  Кривая без истории:10534
  Кривая без истории:10535
  Кривая без истории:10536
  Кривая без истории:10537
  Кривая без истории:10538
  Кривая без истории:10539
  Кривая без истории:10540
  Кривая без истории:10541
  Кривая без истории:10542
  Кривая без истории:10543
  Кривая без истории:10544
  Кривая без истории:10545
  Кривая без истории:10546
  Кривая без истории:10547
  Кривая без истории:10548
  Кривая без истории:10549
  Кривая без истории:10550
  Кривая без истории:10551
  Кривая без истории:10552
  Кривая без истории:10553
  Кривая без истории:10554
  Кривая без истории:10555
  Кривая без истории:10556
  Кривая без истории:10557
  Кривая без истории:10558
  Кривая без истории:10559
  Кривая без истории:10560
  Кривая без истории:10561
  Кривая без истории:10562
  Кривая без истории:10563
  Кривая без истории:10564
  Кривая без истории:10565
  Кривая без истории:10566
  Кривая без истории:10567
  Кривая без истории:10568
  Кривая без истории:10569
  Кривая без истории:10570
  Кривая без истории:10571
  Кривая без истории:10572
  Кривая без истории:10573
  Кривая без истории:10574
  Кривая без истории:10575
  Кривая без истории:10576
  Кривая без истории:10577
  Кривая без истории:10578
  Кривая без истории:10579
  Кривая без истории:10580
  Кривая без истории:10581
  Кривая без истории:10582
  Кривая без истории:10583
  Кривая без истории:10584
  Кривая без истории:10585
  Кривая без истории:10586
  Кривая без истории:10587
  Кривая без истории:10588
  Кривая без истории:10589
  Кривая без истории:10590
  Кривая без истории:10591
  Кривая без истории:10592
  Кривая без истории:10593
  Кривая без истории:10594
  Кривая без истории:10595
  Кривая без истории:10596
  Кривая без истории:10597
  Кривая без истории:10598
  Кривая без истории:10599
  Кривая без истории:10600
  Кривая без истории:10601
  Кривая без истории:10602
  Кривая без истории:10603
  Кривая без истории:10604
  Кривая без истории:10605
  Кривая без истории:10606
  Кривая без истории:10607
  Кривая без истории:10608
  Кривая без истории:10609
  Кривая без истории:10610
  Кривая без истории:10611
  Кривая без истории:10612
  Кривая без истории:10613
  Кривая без истории:10614
  Кривая без истории:10615
  Кривая без истории:10616
  Кривая без истории:10617
  Кривая без истории:10618
  Кривая без истории:10619
  Кривая без истории:10620
  Кривая без истории:10621
  Кривая без истории:10622
  Кривая без истории:10623
  Кривая без истории:10624
  Кривая без истории:10625
  Кривая без истории:10626
  Кривая без истории:10627
  Кривая без истории:10628
  Кривая без истории:10629
  Кривая без истории:10630
  Кривая без истории:10631
  Кривая без истории:10632
  Кривая без истории:10633
  Кривая без истории:10634
  Кривая без истории:10635
  Кривая без истории:10636
  Кривая без истории:10637
  Кривая без истории:10638
  Кривая без истории:10639
  Кривая без истории:10640
  Кривая без истории:10641
  Кривая без истории:10642
  Кривая без истории:10643
  Кривая без истории:10644
  Кривая без истории:10645
  Кривая без истории:10646
  Кривая без истории:10647
  Кривая без истории:10648
  Кривая без истории:10649
  Кривая без истории:10650
  Кривая без истории:10651
  Кривая без истории:10652
  Кривая без истории:10653
  Кривая без истории:10654
  Кривая без истории:10655
  Кривая без истории:10656
  Кривая без истории:10657
  Кривая без истории:10658
  Кривая без истории:10659
  Кривая без истории:10660
  Кривая без истории:10661
  Кривая без истории:10662
  Кривая без истории:10663
  Кривая без истории:10664
  Кривая без истории:10665
  Кривая без истории:10666
  Кривая без истории:10667
  Кривая без истории:10668
  Кривая без истории:10669
  Кривая без истории:10670
  Кривая без истории:10671
  Кривая без истории:10672
  Кривая без истории:10673
  Кривая без истории:10674
  Кривая без истории:10675
  Кривая без истории:10676
  Кривая без истории:10677
  Кривая без истории:10678
  Кривая без истории:10679
  Кривая без истории:10680
  Кривая без истории:10681
  Кривая без истории:10682
  Кривая без истории:10683
  Кривая без истории:10684
  Кривая без истории:10685
  Кривая без истории:10686
  Кривая без истории:10687
  Кривая без истории:10688
  Кривая без истории:10689
  Кривая без истории:10690
  Кривая без истории:10691
  Кривая без истории:10692
  Кривая без истории:10693
  Кривая без истории:10694
  Кривая без истории:10695
  Кривая без истории:10696
  Кривая без истории:10697
  Кривая без истории:10698
  Кривая без истории:10699
  Кривая без истории:10700
  Кривая без истории:10701
  Кривая без истории:10702
  Кривая без истории:10703
  Кривая без истории:10704
  Кривая без истории:10705
  Кривая без истории:10706
  Кривая без истории:10707
  Кривая без истории:10708
  Кривая без истории:10709
  Кривая без истории:10710
  Кривая без истории:10711
  Кривая без истории:10712
  Кривая без истории:10713
  Кривая без истории:10714
  Кривая без истории:10715
  Кривая без истории:10716
  Кривая без истории:10717
  Кривая без истории:10718
  Кривая без истории:10719
  Кривая без истории:10720
  Кривая без истории:10721
  Кривая без истории:10722
  Кривая без истории:10723
  Кривая без истории:10724
  Кривая без истории:10725
  Кривая без истории:10726
  Кривая без истории:10727
  Кривая без истории:10728
  Кривая без истории:10729
  Кривая без истории:10730
  Кривая без истории:10731
  Кривая без истории:10732
  Кривая без истории:10733
  Кривая без истории:10734
  Кривая без истории:10735
  Кривая без истории:10736
  Кривая без истории:10737
  Кривая без истории:10738
  Кривая без истории:10739
  Кривая без истории:10740
  Кривая без истории:10741
  Кривая без истории:10742
  Кривая без истории:10743
  Кривая без истории:10744
  Кривая без истории:10745
  Кривая без истории:10746
  Кривая без истории:10747
  Кривая без истории:10748
  Кривая без истории:10749
  Кривая без истории:10750
  Кривая без истории:10751
  Кривая без истории:10752
  Кривая без истории:10753
  Кривая без истории:10754
  Кривая без истории:10755
  Кривая без истории:10756
  Кривая без истории:10757
  Кривая без истории:10758
  Кривая без истории:10759
  Кривая без истории:10760
  Кривая без истории:10761
  Кривая без истории:10762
